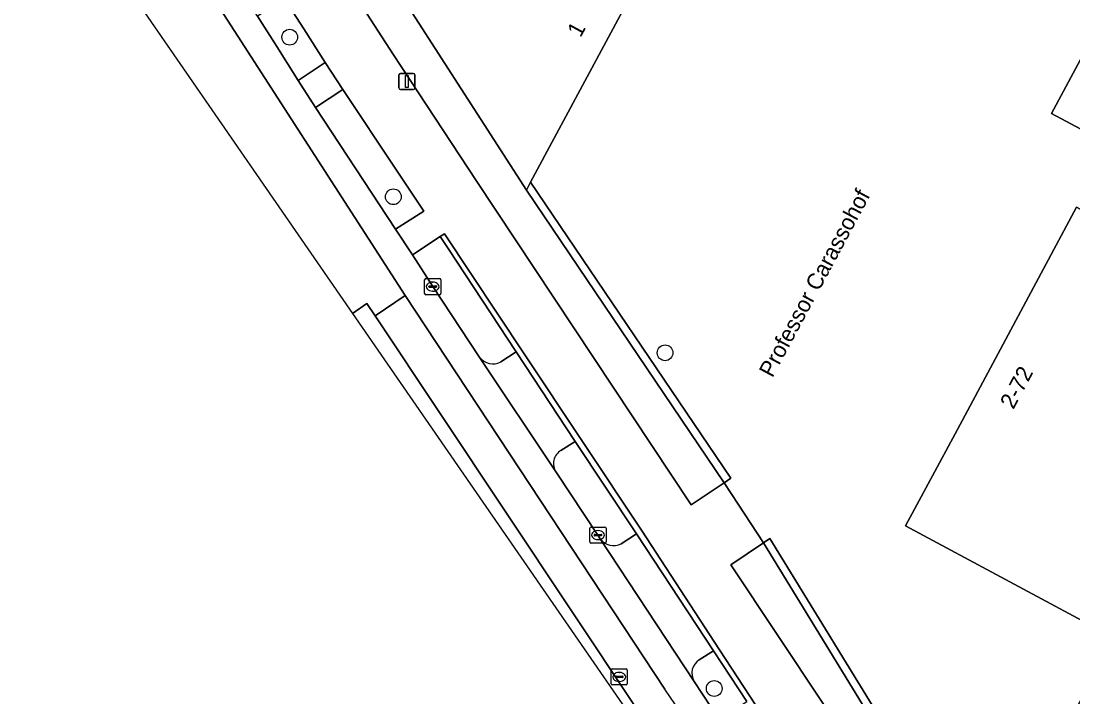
# Model space of a CAD drawing. Extents: x 159489 to 160304, y 383825 to 384531.
# Drawn here: x 159514.8 to 159580.2, y 384216.6 to 384258.6 of the extents above; entities that cross this region are included whole.
import ezdxf

# ---------------------------------------------------------------- set-up
doc = ezdxf.new("R2010")
doc.units = 0
for name, color, linetype in [('IMGEO_Boom', 7, 'Continuous'), ('IMGEO_Erf', 7, 'Continuous'), ('IMGEO_Groenvoorziening', 7, 'Continuous'), ('IMGEO_Kolk', 7, 'Continuous'), ('IMGEO_Lichtmast', 7, 'Continuous'), ('IMGEO_Openbare_ruimte_label', 7, 'Continuous'), ('IMGEO_Pand', 7, 'Continuous'), ('IMGEO_Pand_nummerreeks', 7, 'Continuous'), ('IMGEO_Parkeervlak_open', 7, 'Continuous'), ('IMGEO_Rijbaan_lokaal_gesloten', 7, 'Continuous'), ('IMGEO_Rijbaan_lokaal_open', 7, 'Continuous'), ('IMGEO_Rioolput', 7, 'Continuous'), ('IMGEO_Voetpad_gesloten', 7, 'Continuous'), ('IMGEO_Voetpad_open', 7, 'Continuous')]:
    doc.layers.add(name, color=color, linetype=linetype)

msp = doc.modelspace()

# ---------------------------------------------------------------- linework, layer by layer
at = {"layer": 'IMGEO_Boom'}
for centre in [(159531.469, 384257.566), (159537.915, 384247.646), (159554.816, 384237.946), (159557.872, 384217.076)]:
    msp.add_circle(centre, 0.489, dxfattribs=at)
at = {"layer": 'IMGEO_Erf'}
for points in [[(159631.56, 384209.476), (159640.276, 384225.681), (159611.777, 384241.285), (159616.379, 384249.69), (159600.425, 384258.245), (159593.348, 384245.049), (159582.491, 384250.872), (159578.85, 384252.831), (159587.23, 384268.419), (159590.223, 384274), (159575.933, 384281.657), (159574.935, 384279.809), (159575.127, 384279.7), (159565.449, 384261.675), (159556.176, 384266.653), (159554.827, 384264.14), (159546.454, 384248.546), (159558.913, 384230.144), (159558.499, 384229.864), (159559.363, 384228.538), (159560.934, 384226.137), (159561.341, 384226.407), (159569.144, 384213.675)], [(159574.428, 384204.726), (159582.76, 384220.223), (159569.777, 384227.198), (159572.996, 384233.183), (159580.412, 384246.999), (159595.639, 384238.832), (159585.772, 384220.436), (159598.102, 384213.824)]]:
    msp.add_lwpolyline(points, dxfattribs=at)
at = {"layer": 'IMGEO_Groenvoorziening'}
for points in [[(159546.189, 384248.053), (159536.462, 384263.182), (159534.333, 384266.954), (159532.141, 384265.589), (159535.783, 384259.763), (159537.922, 384256.46), (159543.06, 384248.654), (159556.437, 384228.499), (159558.499, 384229.864)], [(159531.17, 384259.924), (159529.475, 384258.882), (159530.676, 384256.993), (159531.995, 384254.871), (159533.67, 384255.984), (159532.339, 384258.083)], [(159534.768, 384254.316), (159533.078, 384253.19), (159538.058, 384245.622), (159539.805, 384246.756), (159538.106, 384249.307)], [(159546.454, 384248.546), (159546.189, 384248.053), (159558.499, 384229.864), (159558.913, 384230.144)], [(159560.934, 384226.137), (159568.737, 384213.4), (159569.144, 384213.675), (159561.341, 384226.407)], [(159560.934, 384226.137), (159558.905, 384224.769), (159564.664, 384216.096), (159567.101, 384212.363), (159568.737, 384213.4)]]:
    msp.add_lwpolyline(points, close=True, dxfattribs=at)
for points in [[(159540.836, 384245.167), (159539.105, 384244.038), (159540.363, 384242.058), (159543.263, 384237.696)], [(159544.603, 384237.375), (159545.553, 384238.015), (159541.321, 384244.432), (159540.836, 384245.167)], [(159549.217, 384232.423), (159548.342, 384231.88)], [(159552.088, 384226.068), (159553.047, 384226.686), (159549.217, 384232.423)], [(159548.034, 384230.526), (159550.644, 384226.613), (159550.775, 384226.382)], [(159556.624, 384217.517), (159558.184, 384215.145), (159559.903, 384216.259), (159557.829, 384219.423)], [(159557.829, 384219.423), (159556.941, 384218.865)]]:
    msp.add_lwpolyline(points, dxfattribs=at)
for centre, radius, start, end in [((159544.121, 384238.319), 1.06, 216.00906, 297.04799), ((159548.841, 384231.054), 0.965, 121.15353, 213.21599), ((159551.62, 384227.012), 1.054, 216.71097, 296.39), ((159557.483, 384218.026), 0.999, 122.88057, 210.65261)]:
    msp.add_arc(centre, radius, start, end, dxfattribs=at)
at = {"layer": 'IMGEO_Kolk'}
for p, q in [((159539.937, 384242.558), (159540.789, 384242.558)), ((159539.862, 384241.632), (159539.862, 384242.484)), ((159540.121, 384242.052), (159540.121, 384242.064)), ((159540.559, 384242.015), (159540.161, 384242.015)), ((159540.164, 384242.101), (159540.562, 384242.101)), ((159540.35, 384242.338), (159540.375, 384242.338)), ((159540.605, 384242.064), (159540.605, 384242.052)), ((159540.863, 384242.484), (159540.863, 384241.632)), ((159540.789, 384241.558), (159539.937, 384241.558)), ((159540.373, 384241.778), (159540.348, 384241.778)), ((159550.143, 384226.187), (159550.143, 384227.039)), ((159550.218, 384227.113), (159551.07, 384227.113)), ((159550.631, 384226.893), (159550.656, 384226.893)), ((159551.144, 384227.039), (159551.144, 384226.187)), ((159550.402, 384226.607), (159550.402, 384226.619)), ((159550.84, 384226.57), (159550.442, 384226.57)), ((159550.445, 384226.656), (159550.843, 384226.656)), ((159550.654, 384226.333), (159550.629, 384226.333)), ((159550.886, 384226.619), (159550.886, 384226.607)), ((159551.07, 384226.113), (159550.218, 384226.113))]:
    msp.add_line(p, q, dxfattribs=at)
for points in [[(159539.937, 384242.558), (159540.789, 384242.558)], [(159539.862, 384241.632), (159539.862, 384242.484)], [(159540.863, 384242.484), (159540.863, 384241.632)], [(159540.789, 384241.558), (159539.937, 384241.558)], [(159550.143, 384226.187), (159550.143, 384227.039)], [(159550.218, 384227.113), (159551.07, 384227.113)], [(159551.144, 384227.039), (159551.144, 384226.187)], [(159551.07, 384226.113), (159550.218, 384226.113)]]:
    msp.add_lwpolyline(points, dxfattribs=at)
for centre, radius, start, end in [((159539.939, 384242.482), 0.0765, 91.55205, 178.44795), ((159539.939, 384242.482), 0.0765, 91.55205, 178.44795), ((159540.787, 384242.482), 0.0765, 1.55205, 88.44795), ((159540.787, 384242.482), 0.0765, 1.55205, 88.44795), ((159540.161, 384242.061), 0.0403, 85.87752, 175.75265), ((159540.158, 384242.051), 0.0366, 178.93798, 274.71019), ((159540.562, 384242.058), 0.043, 264.86636, 352.45326), ((159540.566, 384242.063), 0.0386, 1.73085, 96.63898), ((159539.939, 384241.634), 0.0765, 181.55205, 268.44795), ((159539.939, 384241.634), 0.0765, 181.55205, 268.44795), ((159540.787, 384241.634), 0.0765, 271.55205, 358.44795), ((159540.787, 384241.634), 0.0765, 271.55205, 358.44795), ((159550.22, 384227.037), 0.0765, 91.55205, 178.44795), ((159550.22, 384227.037), 0.0765, 91.55205, 178.44795), ((159551.068, 384227.037), 0.0765, 1.55205, 88.44795), ((159551.068, 384227.037), 0.0765, 1.55205, 88.44795), ((159550.22, 384226.189), 0.0765, 181.55205, 268.44795), ((159550.22, 384226.189), 0.0765, 181.55205, 268.44795), ((159550.442, 384226.616), 0.0403, 85.87752, 175.75265), ((159550.439, 384226.606), 0.0366, 178.93798, 274.71019), ((159550.843, 384226.613), 0.043, 264.86636, 352.45326), ((159550.847, 384226.618), 0.0386, 1.73085, 96.63898), ((159551.068, 384226.189), 0.0765, 271.55205, 358.44795), ((159551.068, 384226.189), 0.0765, 271.55205, 358.44795)]:
    msp.add_arc(centre, radius, start, end, dxfattribs=at)
for centre, major_axis, ratio, start_param, end_param in [((159540.349, 384242.058), (-0.387, 0.002), 0.722429, 4.712389, 7.853982), ((159540.374, 384242.058), (-0.39, 0.002), 0.717154, 1.570796, 4.712389), ((159550.63, 384226.613), (-0.387, 0.002), 0.722429, 4.712389, 7.853982), ((159550.655, 384226.613), (-0.39, 0.002), 0.717154, 1.570796, 4.712389)]:
    msp.add_ellipse(centre, major_axis=major_axis, ratio=ratio, start_param=start_param, end_param=end_param, dxfattribs=at)
at = {"layer": 'IMGEO_Lichtmast'}
for p, q in [((159538.26, 384254.416), (159538.26, 384255.216)), ((159538.26, 384255.216), (159538.26, 384254.416)), ((159538.36, 384255.316), (159539.15, 384255.316)), ((159539.15, 384255.316), (159538.36, 384255.316)), ((159539.25, 384255.216), (159539.25, 384254.416)), ((159539.25, 384254.416), (159539.25, 384255.216)), ((159539.15, 384254.316), (159538.36, 384254.316)), ((159538.36, 384254.316), (159539.15, 384254.316))]:
    msp.add_line(p, q, dxfattribs=at)
msp.add_lwpolyline([(159538.68, 384255.191), (159538.83, 384255.191), (159538.83, 384254.441), (159538.68, 384254.441), (159538.68, 384255.191)], dxfattribs=at)
for centre, start, end in [((159538.36, 384255.216), 90, 180), ((159538.36, 384255.216), 90, 180), ((159539.15, 384255.216), 0, 90), ((159539.15, 384255.216), 360, 90), ((159538.36, 384254.416), 180, 270), ((159538.36, 384254.416), 180, 270), ((159539.15, 384254.416), 270, 0), ((159539.15, 384254.416), 270, 0)]:
    msp.add_arc(centre, 0.1, start, end, dxfattribs=at)
at = {"layer": 'IMGEO_Pand'}
for points in [[(159590.223, 384274), (159587.23, 384268.419), (159578.85, 384252.831), (159582.491, 384250.872), (159593.348, 384245.049), (159600.425, 384258.245), (159616.379, 384249.69), (159620.712, 384257.605)], [(159554.827, 384264.14), (159545.068, 384269.391), (159541.03, 384271.564), (159540.015, 384269.655), (159539.953, 384269.688), (159536.735, 384263.691), (159536.462, 384263.182), (159546.189, 384248.053), (159546.454, 384248.546)], [(159585.772, 384220.436), (159595.639, 384238.832), (159580.412, 384246.999), (159572.996, 384233.183), (159569.777, 384227.198), (159582.76, 384220.223), (159574.428, 384204.726), (159574.13, 384204.172), (159576.187, 384200.78), (159579.356, 384195.554), (159584.074, 384187.773), (159584.34, 384188.267), (159598.102, 384213.824)]]:
    msp.add_lwpolyline(points, close=True, dxfattribs=at)
at = {"layer": 'IMGEO_Parkeervlak_open'}
for points in [[(159545.553, 384238.015), (159544.603, 384237.375)], [(159548.342, 384231.88), (159549.217, 384232.423), (159545.553, 384238.015)], [(159543.263, 384237.696), (159548.034, 384230.526)], [(159550.775, 384226.382), (159556.624, 384217.517)], [(159553.047, 384226.686), (159552.088, 384226.068)], [(159556.941, 384218.865), (159557.829, 384219.423), (159553.047, 384226.686)]]:
    msp.add_lwpolyline(points, dxfattribs=at)
for centre, radius, start, end in [((159544.121, 384238.319), 1.06, 216.00906, 297.04799), ((159548.841, 384231.054), 0.965, 121.15353, 213.21599), ((159551.62, 384227.012), 1.054, 216.71097, 296.39), ((159557.483, 384218.026), 0.999, 122.88057, 210.65261)]:
    msp.add_arc(centre, radius, start, end, dxfattribs=at)
at = {"layer": 'IMGEO_Rijbaan_lokaal_gesloten'}
for points in [[(159522.428, 384266.788), (159525.931, 384261.215), (159538.641, 384241.501), (159554.807, 384217.036)], [(159564.547, 384205.433), (159563.028, 384207.742), (159560.758, 384211.222), (159560.057, 384212.297), (159558.184, 384215.145), (159556.624, 384217.517), (159550.775, 384226.382), (159550.644, 384226.613), (159548.034, 384230.526), (159543.263, 384237.696), (159540.363, 384242.058), (159539.105, 384244.038), (159538.058, 384245.622), (159533.078, 384253.19), (159531.995, 384254.871), (159530.676, 384256.993), (159529.475, 384258.882), (159528.457, 384260.496), (159527.408, 384262.135), (159527.297, 384262.272), (159527.066, 384262.703)], [(159553.006, 384215.893), (159536.788, 384240.242), (159536.266, 384241.006), (159535.383, 384240.391), (159561.466, 384202.663)]]:
    msp.add_lwpolyline(points, dxfattribs=at)
msp.add_arc((158952.782, 383813.503), 724.757, 30.882688, 33.833641, dxfattribs=at)
at = {"layer": 'IMGEO_Rijbaan_lokaal_open'}
for points in [[(159535.383, 384240.391), (159536.266, 384241.006), (159536.788, 384240.242), (159538.641, 384241.501), (159525.931, 384261.215), (159523.948, 384259.997), (159522.463, 384259.078), (159535.383, 384240.391)], [(159554.807, 384217.036), (159538.641, 384241.501), (159536.788, 384240.242), (159553.006, 384215.893)]]:
    msp.add_lwpolyline(points, dxfattribs=at)
msp.add_arc((158952.782, 383813.503), 724.757, 30.882688, 33.833641, dxfattribs=at)
at = {"layer": 'IMGEO_Rioolput'}
for p, q in [((159551.467, 384217.372), (159551.467, 384218.224)), ((159551.542, 384218.298), (159552.394, 384218.298)), ((159551.726, 384217.792), (159551.726, 384217.804)), ((159552.164, 384217.755), (159551.766, 384217.755)), ((159551.769, 384217.841), (159552.167, 384217.841)), ((159551.955, 384218.078), (159551.98, 384218.078)), ((159552.21, 384217.804), (159552.21, 384217.792)), ((159552.468, 384218.224), (159552.468, 384217.372)), ((159552.394, 384217.298), (159551.542, 384217.298)), ((159551.978, 384217.518), (159551.953, 384217.518))]:
    msp.add_line(p, q, dxfattribs=at)
for points in [[(159551.467, 384217.372), (159551.467, 384218.224)], [(159551.542, 384218.298), (159552.394, 384218.298)], [(159552.468, 384218.224), (159552.468, 384217.372)], [(159552.394, 384217.298), (159551.542, 384217.298)]]:
    msp.add_lwpolyline(points, dxfattribs=at)
for centre, radius, start, end in [((159551.544, 384218.222), 0.0765, 91.55205, 178.44795), ((159551.544, 384218.222), 0.0765, 91.55205, 178.44795), ((159551.766, 384217.801), 0.0403, 85.87752, 175.75265), ((159551.763, 384217.791), 0.0366, 178.93798, 274.71019), ((159552.167, 384217.798), 0.043, 264.86636, 352.45326), ((159552.171, 384217.803), 0.0386, 1.73085, 96.63898), ((159552.392, 384218.222), 0.0765, 1.55205, 88.44795), ((159552.392, 384218.222), 0.0765, 1.55205, 88.44795), ((159551.544, 384217.374), 0.0765, 181.55205, 268.44795), ((159551.544, 384217.374), 0.0765, 181.55205, 268.44795), ((159552.392, 384217.374), 0.0765, 271.55205, 358.44795), ((159552.392, 384217.374), 0.0765, 271.55205, 358.44795)]:
    msp.add_arc(centre, radius, start, end, dxfattribs=at)
for centre, major_axis, ratio, start_param, end_param in [((159551.954, 384217.798), (-0.387, 0.002), 0.722429, 4.712389, 7.853982), ((159551.979, 384217.798), (-0.39, 0.002), 0.717154, 1.570796, 4.712389)]:
    msp.add_ellipse(centre, major_axis=major_axis, ratio=ratio, start_param=start_param, end_param=end_param, dxfattribs=at)
at = {"layer": 'IMGEO_Voetpad_gesloten'}
msp.add_lwpolyline([(159567.124, 384205.873), (159558.212, 384219.486), (159553.341, 384226.923), (159546.045, 384237.884), (159541.101, 384245.34), (159540.836, 384245.167), (159541.321, 384244.432), (159545.553, 384238.015), (159549.217, 384232.423), (159553.047, 384226.686), (159557.829, 384219.423), (159559.903, 384216.259)], dxfattribs=at)
at = {"layer": 'IMGEO_Voetpad_open'}
for points in [[(159543.06, 384248.654), (159537.922, 384256.46), (159535.783, 384259.763), (159532.141, 384265.589), (159534.333, 384266.954), (159531.499, 384271.869), (159529.156, 384270.537), (159524.479, 384278.85), (159521.885, 384283.676), (159520.528, 384286.319), (159516.4, 384294.599), (159514.758, 384298.232)], [(159527.795, 384263.144), (159527.066, 384262.703), (159527.297, 384262.272), (159527.408, 384262.135), (159529.056, 384263.238), (159530.14, 384261.558), (159531.17, 384259.924), (159532.339, 384258.083), (159533.67, 384255.984), (159534.768, 384254.316), (159538.106, 384249.307), (159539.805, 384246.756), (159538.058, 384245.622), (159539.105, 384244.038), (159540.836, 384245.167), (159541.101, 384245.34), (159546.045, 384237.884), (159553.341, 384226.923), (159558.212, 384219.486), (159567.124, 384205.873)], [(159564.664, 384216.096), (159558.905, 384224.769), (159560.934, 384226.137), (159559.363, 384228.538), (159558.499, 384229.864), (159556.437, 384228.499), (159543.06, 384248.654)]]:
    msp.add_lwpolyline(points, dxfattribs=at)
msp.add_lwpolyline([(159533.67, 384255.984), (159531.995, 384254.871), (159533.078, 384253.19), (159534.768, 384254.316)], close=True, dxfattribs=at)

# ---------------------------------------------------------------- texts
at = {"layer": 'IMGEO_Openbare_ruimte_label'}
msp.add_text('Professor Carassohof', height=1, rotation=61.7691, dxfattribs=at).set_placement((159561.491, 384236.351))
at = {"layer": 'IMGEO_Pand_nummerreeks'}
for s, rotation, p in [('1', 61.57004, (159549.558, 384257.501)), ('2-72', 61.76485, (159576.479, 384234.387))]:
    msp.add_text(s, height=1, rotation=rotation, dxfattribs=at).set_placement(p)

doc.saveas('drawing.dxf')
